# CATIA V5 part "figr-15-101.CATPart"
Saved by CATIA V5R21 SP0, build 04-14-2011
Part number: Part1
Bounding box of the stored display mesh (mm): x -52.43 to 60.529, y -25.631 to 32.893, z 0 to 4
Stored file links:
  D:\CATIA V5R21 E-RESOURCES\CATIA-V5R21\catia-v5r21-prt\c15-catia-v5r20-prt\c15-catia-v5r21-figr-15-101.CATPart
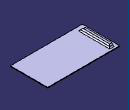
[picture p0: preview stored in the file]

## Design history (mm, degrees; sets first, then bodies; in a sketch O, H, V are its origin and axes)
SheetMetalParameters1: Thickness 1, BendRadius 5, KFactor 0.5 {= log(min(100,max(20*SheetMetalParameters1.BendRadius,SheetMetalParameters1.Thickness)/SheetMetalParameters1.Thickness))/log(100)/2}, ReliefRadialLength 1, ReliefAxialLength 2, MinimumBendRadius 0
Body1 (main body)
  Sketch1 on xy-plane, origin (0, 0, 0), H (1, 0, 0), V (0, 1, 0)
    line L1 (-52.4297, 32.8934) -> (60.5286, 32.8934)
    line L2 (60.5286, 32.8934) -> (60.5286, -25.6312)
    line L3 (60.5286, -25.6312) -> (-52.4297, -25.6312)
    line L4 (-52.4297, -25.6312) -> (-52.4297, 32.8934)
    horizontal: L1 H, L3 H
    vertical: L2 V, L4 V
  Wall1: Thickness 1, Profile Sketch1
  Sketch2 on face of Wall1, origin (0, 0, 1), H (1, 0, 0), V (0, 1, 0)
    line L1 (-47.3159, -16.5837) -> (-43.073, -16.5837)
    line L2 (-43.073, -16.5837) -> (-43.073, 26.788)
    line L3 (-43.073, 26.788) -> (-47.3159, 26.788)
    line L4 (-47.3159, 26.788) -> (-47.3159, -16.5837)
    horizontal: L1 H, L3 H
    vertical: L2 V, L4 V
  d_Stamp1: Stamp_FilletRadius 2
